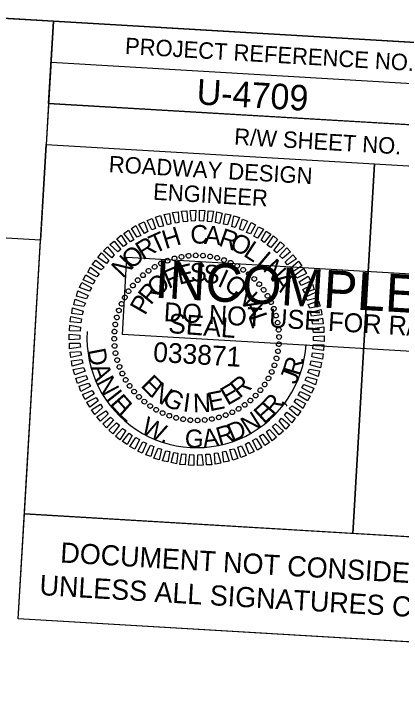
# Model space of a CAD drawing. Extents: x 2010810 to 2012732, y 444258 to 445456.
# Drawn here: x 2012494.2 to 2012611.9, y 445134 to 445346.8 of the extents above; entities that cross this region are included whole.
import ezdxf

# ---------------------------------------------------------------- set-up
doc = ezdxf.new("R2010")
doc.units = 0
for name, color, linetype in [('Old_Level_58', 7, 'Continuous'), ('Scratch_Level_0', 7, 'Continuous'), ('Sheet Clip Boundary CELL', 7, 'Continuous'), ('Sheet Data Field CELL', 7, 'Continuous'), ('Sheet Plan And Profile CELL', 7, 'Continuous'), ('Sheet Professional Seal CELL', 7, 'Continuous'), ('Sheet Profile Grid Minor CELL', 7, 'Continuous'), ('Sheet Sticker Exception Certification CELL', 7, 'Continuous'), ('Sheet Sticker Incomplete CELL', 7, 'Continuous')]:
    doc.layers.add(name, color=color, linetype=linetype)

msp = doc.modelspace()

# ---------------------------------------------------------------- linework, layer by layer
at = {"layer": 'Old_Level_58'}
msp.add_lwpolyline([(2012306.5, 445356.39), (2012506.21, 445344.62), (2012502.28, 445278.05), (2012302.58, 445289.82)], close=True, dxfattribs=at)
at = {"layer": 'Scratch_Level_0'}
msp.add_arc((2012549.76, 445248.34), 33.36, 176.6264, 356.6264, dxfattribs=at)
at = {"layer": 'Sheet Clip Boundary CELL'}
msp.add_lwpolyline([(2011147.85, 444375), (2012145.7, 444317.47), (2012151.4, 444414.1), (2011981.99, 444424.08), (2012065.05, 444531.98), (2012116.09, 444528.98), (2012447, 444433.71), (2012447.13, 444434.15), (2012512.37, 444430.3), (2012650.61, 444422.16), (2012668.12, 444720.33), (2012623.18, 444722.98), (2012629.52, 444823.68), (2012643.65, 445063.27), (2012648.58, 445153.9), (2012495.5, 445162.92), (2012502.28, 445278.05), (2012302.58, 445289.82), (2012278.52, 445262.33), (2012176.97, 445268.45), (2011765.99, 445293.2), (2011771.61, 445387.92), (2011477.93, 445405.24)], dxfattribs=at)
at = {"layer": 'Sheet Plan And Profile CELL'}
for p, q in [((2012505.47, 445332.09), (2012705.17, 445320.32)), ((2012504.73, 445319.61), (2012504, 445307.14)), ((2012504.73, 445319.61), (2012704.44, 445307.84)), ((2012603.87, 445301.25), (2012597.26, 445188.99))]:
    msp.add_line(p, q, dxfattribs=at)
for points in [[(2012705.91, 445332.85), (2011208.51, 445421.12), (2011146.72, 444372.94), (2012644.12, 444284.67)], [(2012506.21, 445344.62), (2012705.91, 445332.85), (2012704.44, 445307.84), (2012504.73, 445319.61)], [(2012504, 445307.14), (2012603.87, 445301.25), (2012597.25, 445188.94), (2012497.38, 445194.83)], [(2012603.87, 445301.25), (2012703.7, 445295.36), (2012697.08, 445183.06), (2012597.25, 445188.94)]]:
    msp.add_lwpolyline(points, close=True, dxfattribs=at)
at = {"layer": 'Sheet Professional Seal CELL'}
for p, q in [((2012549.49, 445273.45), (2012549.49, 445273.45)), ((2012551.69, 445273.37), (2012551.69, 445273.37)), ((2012540.93, 445271.85), (2012540.93, 445271.85)), ((2012542.97, 445272.54), (2012542.97, 445272.54)), ((2012545.11, 445273.01), (2012545.11, 445273.01)), ((2012547.33, 445273.28), (2012547.33, 445273.28)), ((2012553.88, 445273.09), (2012553.88, 445273.09)), ((2012556, 445272.62), (2012556, 445272.62)), ((2012558.07, 445272.05), (2012558.07, 445272.05)), ((2012560.13, 445271.22), (2012560.13, 445271.22)), ((2012536.96, 445269.93), (2012536.96, 445269.93)), ((2012538.93, 445270.97), (2012538.93, 445270.97)), ((2012562.07, 445270.21), (2012562.07, 445270.21)), ((2012563.96, 445269.09), (2012563.96, 445269.09)), ((2012533.41, 445267.39), (2012533.41, 445267.39)), ((2012535.14, 445268.79), (2012535.14, 445268.79)), ((2012565.68, 445267.74), (2012565.68, 445267.74)), ((2012531.82, 445265.93), (2012531.82, 445265.93)), ((2012567.35, 445266.29), (2012567.35, 445266.29)), ((2012530.37, 445264.26), (2012530.37, 445264.26)), ((2012568.81, 445264.7), (2012568.81, 445264.7)), ((2012570.21, 445262.97), (2012570.21, 445262.97)), ((2012527.9, 445260.65), (2012527.9, 445260.65)), ((2012529.01, 445262.54), (2012529.01, 445262.54)), ((2012571.35, 445261.15), (2012571.35, 445261.15)), ((2012526.88, 445258.71), (2012526.88, 445258.71)), ((2012572.39, 445259.18), (2012572.39, 445259.18)), ((2012526.06, 445256.65), (2012526.06, 445256.65)), ((2012573.27, 445257.18), (2012573.27, 445257.18)), ((2012525.49, 445254.58), (2012525.49, 445254.58)), ((2012573.95, 445255.13), (2012573.95, 445255.13)), ((2012525.01, 445252.46), (2012525.01, 445252.46)), ((2012574.43, 445253), (2012574.43, 445253)), ((2012524.73, 445250.27), (2012524.73, 445250.27)), ((2012574.7, 445250.78), (2012574.7, 445250.78)), ((2012524.65, 445248.07), (2012524.65, 445248.07)), ((2012549.76, 445248.34), (2012549.76, 445248.34)), ((2012574.87, 445248.62), (2012574.87, 445248.62)), ((2012524.83, 445245.91), (2012524.83, 445245.91)), ((2012574.79, 445246.42), (2012574.79, 445246.42)), ((2012525.1, 445243.69), (2012525.1, 445243.69)), ((2012574.51, 445244.23), (2012574.51, 445244.23)), ((2012525.57, 445241.56), (2012525.57, 445241.56)), ((2012574.04, 445242.1), (2012574.04, 445242.1)), ((2012526.25, 445239.51), (2012526.25, 445239.51)), ((2012573.46, 445240.03), (2012573.46, 445240.03)), ((2012527.14, 445237.51), (2012527.14, 445237.51)), ((2012572.64, 445237.98), (2012572.64, 445237.98)), ((2012528.17, 445235.54), (2012528.17, 445235.54)), ((2012571.63, 445236.04), (2012571.63, 445236.04)), ((2012529.32, 445233.72), (2012529.32, 445233.72)), ((2012570.51, 445234.15), (2012570.51, 445234.15)), ((2012530.72, 445231.99), (2012530.72, 445231.99)), ((2012569.16, 445232.42), (2012569.16, 445232.42)), ((2012532.18, 445230.4), (2012532.18, 445230.4)), ((2012533.84, 445228.95), (2012533.84, 445228.95)), ((2012566.12, 445229.3), (2012566.12, 445229.3)), ((2012567.71, 445230.76), (2012567.71, 445230.76)), ((2012535.57, 445227.59), (2012535.57, 445227.59)), ((2012562.56, 445226.75), (2012562.56, 445226.75)), ((2012564.39, 445227.9), (2012564.39, 445227.9)), ((2012537.45, 445226.48), (2012537.45, 445226.48)), ((2012539.4, 445225.46), (2012539.4, 445225.46)), ((2012541.45, 445224.64), (2012541.45, 445224.64)), ((2012558.59, 445224.83), (2012558.59, 445224.83)), ((2012560.6, 445225.72), (2012560.6, 445225.72)), ((2012543.52, 445224.07), (2012543.52, 445224.07)), ((2012545.65, 445223.59), (2012545.65, 445223.59)), ((2012547.84, 445223.31), (2012547.84, 445223.31)), ((2012550.04, 445223.23), (2012550.04, 445223.23)), ((2012552.2, 445223.41), (2012552.2, 445223.41)), ((2012554.42, 445223.68), (2012554.42, 445223.68)), ((2012556.55, 445224.15), (2012556.55, 445224.15))]:
    msp.add_line(p, q, dxfattribs=at)
for points in [[(2012540.87, 445282.73), (2012539.9, 445285.79), (2012541.47, 445286.15), (2012541.94, 445283.01)], [(2012543.3, 445283.23), (2012542.44, 445286.44), (2012544.16, 445286.69), (2012544.37, 445283.42)], [(2012545.73, 445283.64), (2012545.12, 445286.88), (2012546.78, 445286.94), (2012546.94, 445283.72)], [(2012548.15, 445283.8), (2012547.79, 445287.03), (2012549.49, 445287.13), (2012549.35, 445283.88)], [(2012550.66, 445283.9), (2012550.6, 445287.16), (2012552.24, 445287.02), (2012551.85, 445283.78)], [(2012553.05, 445283.71), (2012553.24, 445286.96), (2012554.89, 445286.81), (2012554.24, 445283.59)], [(2012555.54, 445283.41), (2012555.93, 445286.65), (2012557.56, 445286.25), (2012556.72, 445283.14)], [(2012536.12, 445281.15), (2012534.69, 445284.04), (2012536.28, 445284.65), (2012537.24, 445281.54)], [(2012538.38, 445282.07), (2012537.25, 445285.04), (2012538.78, 445285.55), (2012539.64, 445282.3)], [(2012557.91, 445282.87), (2012558.55, 445286.04), (2012560.18, 445285.7), (2012559.1, 445282.65)], [(2012560.42, 445282.18), (2012561.11, 445285.39), (2012562.79, 445284.89), (2012561.46, 445281.86)], [(2012562.78, 445281.39), (2012563.71, 445284.44), (2012565.23, 445283.85), (2012563.81, 445280.97)], [(2012531.63, 445278.96), (2012529.94, 445281.62), (2012531.29, 445282.49), (2012532.77, 445279.5)], [(2012533.9, 445280.08), (2012532.22, 445282.89), (2012533.81, 445283.59), (2012534.89, 445280.63)], [(2012564.97, 445280.35), (2012566.31, 445283.43), (2012567.67, 445282.75), (2012566.1, 445279.94)], [(2012567.16, 445279.27), (2012568.58, 445282.14), (2012570.09, 445281.35), (2012568.23, 445278.66)], [(2012529.65, 445277.58), (2012527.64, 445280.1), (2012529.05, 445281.07), (2012530.63, 445278.17)], [(2012569.39, 445277.99), (2012570.91, 445280.76), (2012572.35, 445279.82), (2012570.3, 445277.34)], [(2012525.81, 445274.5), (2012523.39, 445276.7), (2012524.7, 445277.77), (2012526.66, 445275.25)], [(2012527.56, 445276.15), (2012525.49, 445278.47), (2012526.76, 445279.6), (2012528.55, 445276.79)], [(2012571.26, 445276.53), (2012573.18, 445279.32), (2012574.41, 445278.2), (2012572.32, 445275.86)], [(2012523.95, 445272.71), (2012521.47, 445274.8), (2012522.65, 445276.04), (2012524.7, 445273.56)], [(2012573.22, 445274.91), (2012575.23, 445277.55), (2012576.46, 445276.37), (2012574.12, 445274.16)], [(2012575.02, 445273.25), (2012577.22, 445275.73), (2012578.35, 445274.46), (2012575.93, 445272.45)], [(2012522.34, 445270.9), (2012519.75, 445272.75), (2012520.78, 445274.14), (2012523.05, 445271.81)], [(2012576.72, 445271.4), (2012579, 445273.62), (2012580.13, 445272.35), (2012577.42, 445270.56)], [(2012520.73, 445268.99), (2012518.02, 445270.65), (2012519.1, 445271.99), (2012521.58, 445269.84)], [(2012578.36, 445269.5), (2012580.79, 445271.61), (2012581.75, 445270.2), (2012579, 445268.46)], [(2012519.4, 445266.91), (2012516.63, 445268.33), (2012517.47, 445269.83), (2012520.06, 445267.83)], [(2012579.74, 445267.46), (2012582.31, 445269.42), (2012583.17, 445267.91), (2012580.28, 445266.48)], [(2012518.27, 445264.68), (2012515.24, 445266.01), (2012516.08, 445267.51), (2012518.83, 445265.74)], [(2012580.92, 445265.34), (2012583.67, 445267.08), (2012584.53, 445265.53), (2012581.56, 445264.3)], [(2012517.14, 445262.54), (2012514.1, 445263.62), (2012514.84, 445265.13), (2012517.75, 445263.55)], [(2012582.09, 445263.07), (2012584.98, 445264.65), (2012585.54, 445263.06), (2012582.63, 445262.08)], [(2012516.25, 445260.19), (2012513.2, 445261.02), (2012513.64, 445262.64), (2012516.71, 445261.21)], [(2012582.96, 445260.86), (2012585.99, 445262.19), (2012586.54, 445260.55), (2012583.39, 445259.73)], [(2012515.46, 445257.83), (2012512.39, 445258.41), (2012512.84, 445260.09), (2012515.92, 445258.85)], [(2012583.72, 445258.46), (2012586.84, 445259.58), (2012587.3, 445258), (2012584.15, 445257.39)], [(2012514.91, 445255.31), (2012511.74, 445255.79), (2012512.04, 445257.48), (2012515.23, 445256.49)], [(2012584.37, 445256.02), (2012587.64, 445256.98), (2012587.84, 445255.32), (2012584.66, 445254.95)], [(2012514.52, 445252.93), (2012511.28, 445253.22), (2012511.48, 445254.86), (2012514.69, 445254.12)], [(2012584.83, 445253.59), (2012588.03, 445254.35), (2012588.23, 445252.64), (2012585.07, 445252.52)], [(2012514.32, 445250.43), (2012511.07, 445250.47), (2012511.17, 445252.17), (2012514.4, 445251.63)], [(2012585.14, 445251.17), (2012588.43, 445251.67), (2012588.48, 445249.97), (2012585.27, 445249.96)], [(2012514.23, 445247.93), (2012510.96, 445247.73), (2012510.96, 445249.43), (2012514.2, 445249.14)], [(2012585.3, 445248.75), (2012588.57, 445248.96), (2012588.57, 445247.26), (2012585.33, 445247.55)], [(2012514.39, 445245.52), (2012511.1, 445245.01), (2012511.05, 445246.72), (2012514.26, 445246.73)], [(2012585.2, 445246.25), (2012588.45, 445246.21), (2012588.35, 445244.52), (2012585.13, 445245.06)], [(2012514.69, 445243.1), (2012511.49, 445242.34), (2012511.29, 445244.05), (2012514.46, 445244.16)], [(2012585, 445243.76), (2012588.24, 445243.47), (2012588.05, 445241.83), (2012584.83, 445242.57)], [(2012515.15, 445240.67), (2012511.89, 445239.71), (2012511.69, 445241.37), (2012514.86, 445241.74)], [(2012584.61, 445241.38), (2012587.79, 445240.89), (2012587.49, 445239.21), (2012584.29, 445240.2)], [(2012515.81, 445238.22), (2012512.69, 445237.11), (2012512.23, 445238.69), (2012515.37, 445239.3)], [(2012584.06, 445238.86), (2012587.14, 445238.28), (2012586.69, 445236.6), (2012583.6, 445237.83)], [(2012516.57, 445235.83), (2012513.54, 445234.5), (2012512.98, 445236.14), (2012516.13, 445236.95)], [(2012583.27, 445236.5), (2012586.33, 445235.67), (2012585.88, 445234.04), (2012582.81, 445235.48)], [(2012517.44, 445233.62), (2012514.54, 445232.04), (2012513.98, 445233.62), (2012516.9, 445234.6)], [(2012582.38, 445234.15), (2012585.43, 445233.07), (2012584.69, 445231.56), (2012581.77, 445233.13)], [(2012518.61, 445231.35), (2012515.85, 445229.61), (2012514.99, 445231.16), (2012517.97, 445232.39)], [(2012581.26, 445232.01), (2012584.28, 445230.68), (2012583.44, 445229.18), (2012580.69, 445230.94)], [(2012519.79, 445229.22), (2012517.22, 445227.27), (2012516.35, 445228.78), (2012519.24, 445230.21)], [(2012580.12, 445229.78), (2012582.89, 445228.36), (2012582.05, 445226.86), (2012579.47, 445228.86)], [(2012521.17, 445227.19), (2012518.74, 445225.08), (2012517.77, 445226.49), (2012520.53, 445228.23)], [(2012578.8, 445227.7), (2012581.51, 445226.04), (2012580.42, 445224.7), (2012577.95, 445226.85)], [(2012522.81, 445225.29), (2012520.52, 445223.07), (2012519.4, 445224.34), (2012522.11, 445226.13)], [(2012577.18, 445225.79), (2012579.78, 445223.94), (2012578.74, 445222.54), (2012576.48, 445224.88)], [(2012524.5, 445223.44), (2012522.3, 445220.96), (2012521.18, 445222.23), (2012523.6, 445224.24)], [(2012526.31, 445221.78), (2012524.3, 445219.14), (2012523.07, 445220.32), (2012525.4, 445222.53)], [(2012575.57, 445223.98), (2012578.05, 445221.88), (2012576.88, 445220.65), (2012574.82, 445223.13)], [(2012528.27, 445220.16), (2012526.35, 445217.37), (2012525.11, 445218.49), (2012527.2, 445220.82)], [(2012571.97, 445220.54), (2012574.03, 445218.21), (2012572.76, 445217.09), (2012570.98, 445219.9)], [(2012573.72, 445222.19), (2012576.14, 445219.99), (2012574.82, 445218.92), (2012572.87, 445221.44)], [(2012530.13, 445218.7), (2012528.62, 445215.93), (2012527.17, 445216.87), (2012529.22, 445219.35)], [(2012569.88, 445219.11), (2012571.88, 445216.59), (2012570.47, 445215.62), (2012568.89, 445218.52)], [(2012532.36, 445217.41), (2012530.94, 445214.54), (2012529.44, 445215.33), (2012531.3, 445218.03)], [(2012534.55, 445216.33), (2012533.22, 445213.26), (2012531.86, 445213.94), (2012533.43, 445216.75)], [(2012565.62, 445216.61), (2012567.31, 445213.8), (2012565.72, 445213.09), (2012564.64, 445216.06)], [(2012567.89, 445217.72), (2012569.59, 445215.07), (2012568.24, 445214.2), (2012566.76, 445217.19)], [(2012536.75, 445215.3), (2012535.81, 445212.25), (2012534.3, 445212.84), (2012535.72, 445215.71)], [(2012539.1, 445214.51), (2012538.41, 445211.3), (2012536.74, 445211.8), (2012538.07, 445214.82)], [(2012541.62, 445213.81), (2012540.98, 445210.65), (2012539.35, 445210.99), (2012540.43, 445214.03)], [(2012558.65, 445213.96), (2012559.63, 445210.9), (2012558.05, 445210.54), (2012557.59, 445213.67)], [(2012561.15, 445214.62), (2012562.27, 445211.64), (2012560.74, 445211.13), (2012559.88, 445214.39)], [(2012563.41, 445215.53), (2012564.84, 445212.64), (2012563.25, 445212.04), (2012562.28, 445215.15)], [(2012543.99, 445213.27), (2012543.6, 445210.04), (2012541.97, 445210.44), (2012542.8, 445213.54)], [(2012546.48, 445212.98), (2012546.28, 445209.73), (2012544.64, 445209.88), (2012545.28, 445213.1)], [(2012548.87, 445212.78), (2012548.93, 445209.53), (2012547.28, 445209.67), (2012547.67, 445212.91)], [(2012551.38, 445212.89), (2012551.74, 445209.66), (2012550.03, 445209.56), (2012550.17, 445212.81)], [(2012553.79, 445213.05), (2012554.4, 445209.8), (2012552.75, 445209.75), (2012552.59, 445212.97)], [(2012556.22, 445213.45), (2012557.08, 445210.25), (2012555.37, 445210), (2012555.16, 445213.27)]]:
    msp.add_lwpolyline(points, close=True, dxfattribs=at)
for centre, major_axis in [((2012545.14, 445272.99), (-0.133, 0.708)), ((2012547.3, 445273.3), (-0.071, 0.717)), ((2012549.49, 445273.42), (-0.008, 0.72)), ((2012551.68, 445273.35), (0.055, 0.718)), ((2012553.85, 445273.09), (0.117, 0.71)), ((2012555.99, 445272.64), (0.179, 0.697)), ((2012538.92, 445270.96), (-0.311, 0.649)), ((2012540.93, 445271.82), (-0.254, 0.674)), ((2012543.01, 445272.5), (-0.194, 0.693)), ((2012558.08, 445272), (0.239, 0.679)), ((2012560.11, 445271.19), (0.297, 0.656)), ((2012535.15, 445268.73), (-0.419, 0.585)), ((2012536.99, 445269.93), (-0.367, 0.62)), ((2012562.06, 445270.2), (0.353, 0.627)), ((2012563.92, 445269.04), (0.407, 0.594)), ((2012533.43, 445267.38), (-0.469, 0.546)), ((2012565.67, 445267.73), (0.457, 0.557)), ((2012567.3, 445266.27), (0.504, 0.515)), ((2012530.38, 445264.25), (-0.557, 0.457)), ((2012531.84, 445265.88), (-0.515, 0.504)), ((2012568.8, 445264.67), (0.546, 0.469)), ((2012529.06, 445262.5), (-0.594, 0.407)), ((2012570.15, 445262.95), (0.585, 0.419)), ((2012527.91, 445260.65), (-0.627, 0.353)), ((2012571.34, 445261.12), (0.62, 0.367)), ((2012526.92, 445258.69), (-0.656, 0.297)), ((2012572.38, 445259.19), (0.649, 0.311)), ((2012526.1, 445256.66), (-0.679, 0.239)), ((2012573.24, 445257.18), (0.674, 0.254)), ((2012525.47, 445254.57), (-0.697, 0.179)), ((2012573.92, 445255.1), (0.693, 0.194)), ((2012525.02, 445252.43), (-0.71, 0.117)), ((2012574.41, 445252.97), (0.708, 0.133)), ((2012524.76, 445250.26), (-0.718, 0.055)), ((2012574.72, 445250.8), (0.717, 0.071)), ((2012524.68, 445248.07), (-0.72, -0.008)), ((2012574.84, 445248.62), (0.72, 0.008)), ((2012524.8, 445245.89), (-0.717, -0.071)), ((2012574.77, 445246.43), (0.718, -0.055)), ((2012525.11, 445243.72), (-0.708, -0.133)), ((2012574.51, 445244.26), (0.71, -0.117)), ((2012525.61, 445241.59), (-0.693, -0.194)), ((2012574.06, 445242.12), (0.697, -0.179)), ((2012526.29, 445239.51), (-0.674, -0.254)), ((2012573.42, 445240.02), (0.679, -0.239)), ((2012527.15, 445237.5), (-0.649, -0.311)), ((2012572.61, 445237.99), (0.656, -0.297)), ((2012528.18, 445235.57), (-0.62, -0.367)), ((2012571.62, 445236.04), (0.627, -0.353)), ((2012529.38, 445233.73), (-0.585, -0.419)), ((2012569.15, 445232.43), (0.557, -0.457)), ((2012570.46, 445234.18), (0.594, -0.407)), ((2012530.73, 445232.01), (-0.546, -0.469)), ((2012532.22, 445230.42), (-0.504, -0.515)), ((2012567.69, 445230.8), (0.515, -0.504)), ((2012533.85, 445228.96), (-0.457, -0.557)), ((2012564.37, 445227.96), (0.419, -0.585)), ((2012566.09, 445229.31), (0.469, -0.546)), ((2012535.6, 445227.64), (-0.407, -0.594)), ((2012537.46, 445226.49), (-0.353, -0.627)), ((2012560.61, 445225.73), (0.311, -0.649)), ((2012562.54, 445226.76), (0.367, -0.62)), ((2012539.41, 445225.5), (-0.297, -0.656)), ((2012541.44, 445224.68), (-0.239, -0.679)), ((2012543.54, 445224.05), (-0.179, -0.697)), ((2012554.39, 445223.69), (0.133, -0.708)), ((2012556.52, 445224.19), (0.194, -0.693)), ((2012558.6, 445224.87), (0.254, -0.674)), ((2012545.68, 445223.6), (-0.117, -0.71)), ((2012547.85, 445223.34), (-0.055, -0.718)), ((2012550.04, 445223.27), (0.008, -0.72)), ((2012552.22, 445223.38), (0.071, -0.717))]:
    msp.add_ellipse(centre, major_axis=major_axis, ratio=0.999708, dxfattribs=at)
at = {"layer": 'Sheet Sticker Exception Certification CELL'}
for p, q in [((2012495.5, 445162.92), (2012497.38, 445194.85)), ((2012497.38, 445194.85), (2012697.08, 445183.08)), ((2012695.2, 445151.15), (2012495.5, 445162.92))]:
    msp.add_line(p, q, dxfattribs=at)
at = {"layer": 'Sheet Sticker Incomplete CELL'}
msp.add_lwpolyline([(2012527.19, 445249.42), (2012528.57, 445272.88), (2012675.32, 445264.23), (2012673.94, 445240.77)], close=True, dxfattribs=at)

# ---------------------------------------------------------------- texts
at = {"layer": 'Sheet Data Field CELL'}
msp.add_text('U-4709', height=7.75, rotation=356.6264, dxfattribs=at).set_placement((2012549.59, 445319.32))
at = {"layer": 'Sheet Plan And Profile CELL'}
for s, height, p in [('PROJECT REFERENCE NO.', 5.0001, (2012527.86, 445334.63)), ('R/W SHEET NO.', 5.0001, (2012561.09, 445307.08)), ('ROADWAY DESIGN', 5.0001, (2012522.93, 445298.71)), ('ENGINEER', 5, (2012536.42, 445290.35))]:
    msp.add_text(s, height=height, rotation=356.6264, dxfattribs=at).set_placement(p)
at = {"layer": 'Sheet Professional Seal CELL'}
for s, height, rotation, p in [('H', 5.64, 17.2459, (2012540.28, 445275.3)), ('C', 5.64, 2.8463, (2012547.99, 445276.85)), ('A', 5.64, 355.6467, (2012551.95, 445276.91)), ('T', 5.64, 24.4462, (2012536.94, 445273.84)), ('R', 5.64, 341.2475, (2012556.13, 445276.47)), ('O', 5.64, 334.0476, (2012559.43, 445275.52)), ('R', 5.64, 31.6469, (2012533.42, 445271.85)), ('L', 5.64, 326.8473, (2012563.71, 445273.42)), ('O', 5.64, 38.8482, (2012529.79, 445268.95)), ('N', 5.64, 46.0499, (2012527.32, 445266.2)), ('I', 5.64, 319.6466, (2012567.61, 445270.78)), ('S', 5.64, 3.882, (2012547.96, 445265.33)), ('N', 5.64, 312.4453, (2012569.67, 445269.11)), ('F', 5.64, 22.5935, (2012541.17, 445263.18)), ('E', 5.64, 13.2375, (2012544.45, 445264.48)), ('S', 5.64, 354.5268, (2012551.56, 445265.17)), ('O', 5.64, 41.3077, (2012537.7, 445260.42)), ('I', 5.64, 335.816, (2012555.81, 445264.22)), ('O', 5.64, 326.4599, (2012557.76, 445263.4)), ('A', 5.64, 305.2436, (2012572.44, 445265.99)), ('R', 5.64, 50.6661, (2012535.81, 445258.08)), ('N', 5.64, 317.103, (2012560.99, 445261.21)), ('P', 5.64, 60.0253, (2012534.03, 445254.98)), ('A', 5.64, 298.3867, (2012563.68, 445258.44)), ('SEAL', 5.998, 355.6264, (2012540.99, 445249.86)), ('L', 5.64, 289.0273, (2012565.42, 445254.88)), ('E', 5.64, 314.9033, (2012532.47, 445233.69)), ('R', 5.64, 39.1078, (2012562.79, 445229.79)), ('N', 5.64, 324.2604, (2012535.31, 445230.81)), ('E', 5.64, 29.7505, (2012559.11, 445227.66)), ('G', 5.64, 333.6167, (2012538.97, 445228.34)), ('I', 5.64, 352.3276, (2012545.39, 445226.06)), ('N', 5.64, 1.6828, (2012548.73, 445225.72)), ('E', 5.64, 11.0382, (2012553.71, 445226.02))]:
    msp.add_text(s, height=height, rotation=rotation, dxfattribs=at).set_placement(p)
at = {"layer": 'Sheet Profile Grid Minor CELL'}
for s, height, rotation, p in [('033871', 5.998, 356.6264, (2012536.42, 445241.11)), ('D', 5.5, 280.8946, (2012516.5, 445244.65)), ('R', 5.5, 73.9805, (2012581.1, 445236.58)), ('.', 5.5, 80.9069, (2012582.29, 445240.44)), ('A', 5.5, 290.0393, (2012517.51, 445239.41)), ('J', 5.5, 69.1119, (2012579.98, 445233.96)), ('N', 5.5, 298.2251, (2012519.11, 445234.91)), ('I', 5.5, 308.1568, (2012521.88, 445229.82)), ('E', 5.5, 311.6772, (2012523.07, 445228.15)), ('R', 5.5, 49.0052, (2012573.2, 445224.45)), ('L', 5.5, 318.2602, (2012525.56, 445225.22)), ('E', 5.5, 42.4222, (2012570.3, 445221.92)), (',', 5.5, 55.9317, (2012575.91, 445227.45)), ('W', 5.5, 333.5156, (2012532.5, 445219.67)), ('N', 5.5, 32.4905, (2012565.44, 445218.77)), ('D', 5.5, 23.3459, (2012560.54, 445216.66)), ('G', 5.5, 358.3019, (2012546.11, 445215.07)), ('A', 5.5, 8.2337, (2012551.91, 445214.94)), ('R', 5.5, 16.4194, (2012556.64, 445215.59)), ('.', 5.5, 345.1217, (2012538.62, 445216.78))]:
    msp.add_text(s, height=height, rotation=rotation, dxfattribs=at).set_placement(p)
at = {"layer": 'Sheet Sticker Exception Certification CELL'}
for s, p in [('DOCUMENT NOT CONSIDERED FINAL', (2012508.16, 445180.11)), ('UNLESS ALL SIGNATURES COMPLETED', (2012501.83, 445170.2))]:
    msp.add_text(s, height=6.124, rotation=356.6264, dxfattribs=at).set_placement(p)
at = {"layer": 'Sheet Sticker Incomplete CELL'}
for s, height, p in [('INCOMPLETE PLANS', 11.52, (2012536.81, 445260.57)), ('DO NOT USE FOR R/W ACQUISITION', 5.76, (2012539.65, 445253.45))]:
    msp.add_text(s, height=height, rotation=356.6264, dxfattribs=at).set_placement(p)

doc.saveas('drawing.dxf')
